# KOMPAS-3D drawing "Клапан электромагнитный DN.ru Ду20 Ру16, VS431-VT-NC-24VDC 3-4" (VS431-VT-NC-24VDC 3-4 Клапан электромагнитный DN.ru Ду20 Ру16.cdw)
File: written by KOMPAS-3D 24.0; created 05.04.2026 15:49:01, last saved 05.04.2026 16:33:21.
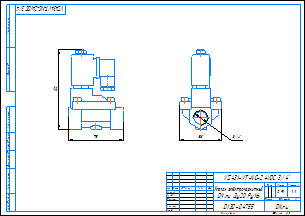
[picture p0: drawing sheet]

Document properties: c3d_UniqueCompID: ef56311e-7521-43dc-8291-0e6108b3d81d; Автор: artio; Класс точности: c; Знак неуказанной шероховатости: Шероховатость не задана; Рассекать на разрезах: Да; Автор: artio; Форматы листов документа: A3; Полное имя файла: VS431-VT-NC-24VDC 3-4 Клапан электромагнитный DN.ru Ду20 Ру16.m3d; Масса: 0.907; Наименование: Клапан электромагнитный DN.ru Ду20 Ру16; Количество листов документа: 1; Примечание: D130-04755

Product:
- Body: Тело 1  | qty 1
    Масса: 1.198355
- Part/product: Клапан электромагнитный DN.ru Ду20 Ру16  | designation VS431-VT-NC-24VDC 3-4
    Масса: 0.907
    Раздел спецификации: Прочие изделия
    Примечание: D130-04755
    additional columns: ef56311e-7521-43dc-8291-0e6108b3d81d; artio; c; Шероховатость не задана; Да

Views: Вид 1, Спереди, Проекционный вид 2
Referenced files in C:\Users\artio\OneDrive\Рабочий стол\Клапан электромагнитный DN.ru\VS431\VS431-ET-NC\: VS431-ET-NC-24VDC 3-4 Клапан электромагнитный DN.ru Ду20 Ру16.m3d
Referenced files in C:\Users\artio\OneDrive\Рабочий стол\Клапан электромагнитный DN.ru\VS431\VS431-VT-NC\: VS431-VT-NC-24VDC 3-4 Клапан электромагнитный DN.ru Ду20 Ру16.m3d
Referenced files in C:\Users\artio\OneDrive\Рабочий стол\Клапан электромагнитный DN.ru\VS431\VS431-NT-NC\: VS431-NT-NC-24VDC 3-4 Клапан электромагнитный DN.ru Ду20 Ру16.cdw
Referenced files in C:\Users\artio\OneDrive\Рабочий стол\Клапан электромагнитный DN.ru\VS431\VS431-VT-NC\VS431-VT-NC-24VDC\Ду20\: VS431-VT-NC-24VDC 3-4 Клапан электромагнитный DN.ru Ду20 Ру16.m3d
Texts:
  VS431-VT-NC-24VDC 3-4
  Клапан электромагнитный
  DN.ru Ду20 Ру16
  VS431-VT-NC-24VDC 3/4"
  VS431-VT-NC-24VDC 3/4"-
  Клапан электромагнитный DN.ru Ду20 Ру16
  VS431-VT-NC-24VDC 3-4 Клапан электромагнитный DN.ru Ду20 Ру16
Dimensions and other numbers on the sheet: 0; 3; 2; 4; 58; 3/4"; 75; 110; 1:1; 1; 0,91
